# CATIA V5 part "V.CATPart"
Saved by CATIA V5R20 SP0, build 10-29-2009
Part number: V带轮
Material "无"
Material "Hall reflection"
Bounding box of the stored display mesh (mm): x -85 to 85, y -159.954 to 180.848, z -36.463 to 17.581
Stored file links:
  D:\liandongzhou\V.CATPart
  D:\catiaM\win_b64\startup\materials\Advanced_Materials.CATMaterial
  D:\catiaM\win_b64\startup\materials\shaders\CATIA_Environment_CUBEMap_Street_1024.dds
  D:\catiaM\win_b64\startup\materials\shaders\CATIA_Metal_Polished.cgfx
  D:\catiaM\win_b64\startup\materials\shaders\CATIA_Diffuse_2DMap_Fiber_256.dds
  D:\catiaM\win_b64\startup\materials\shaders\CATIA_Normal_2DMap_Fiber_1024.dds
  D:\catiaM\win_b64\startup\materials\shaders\CATIA_Leather_Rough.cgfx
  D:\catiaM\win_b64\startup\materials\textures\dot_grid2.png
  D:\catiaM\win_b64\startup\materials\textures\hex_grid.png
  D:\catiaM\win_b64\startup\materials\shaders\CATIA_Environment_2DMap_Street_2048.dds
  D:\catiaM\win_b64\startup\materials\shaders\CATIA_Normal_2DMap_Scratches_1024.dds
  D:\catiaM\win_b64\startup\materials\shaders\CATIA_Metal_Brushed.cgfx
  D:\catiaM\win_b64\startup\materials\environment_map\CATIA_Environment_2DMap_LightRedSatin_256.jpg
  D:\catiaM\win_b64\startup\materials\environment_map\CATIA_Environment_2DMap_DarkRedSatin_256.jpg
  D:\catiaM\win_b64\startup\materials\environment_map\CATIA_Environment_2DMap_Chroma1_256.jpg
  D:\catiaM\win_b64\startup\materials\textures\dot_grid.png
  D:\catiaM\win_b64\startup\materials\shaders\CATIA_Environment_2DMap_Hall_2048.dds
  D:\catiaM\win_b64\startup\materials\shaders\CATIA_Normal_2DMap_MZDotGrid_1024.dds
  D:\catiaM\win_b64\startup\materials\shaders\CATIA_Opacity_2DMap_MZDotGrid_1024.dds
  D:\catiaM\win_b64\startup\materials\shaders\CATIA_Metal_Grid.cgfx
  D:\catiaM\win_b64\startup\materials\environment_map\CATIA_Environment_2DMap_Satin_256.jpg
  D:\catiaM\win_b64\startup\materials\shaders\CATIA_Normal_2DMap_Leather_1024.dds
  D:\catiaM\win_b64\startup\materials\shaders\CATIA_Normal_2DMap_Noisemm_1024.dds
  D:\catiaM\win_b64\startup\materials\shaders\CATIA_Leather_BRDF.cgfx
  D:\catiaM\win_b64\startup\materials\shaders\CATIA_Plastic_Matt.cgfx
  D:\catiaM\win_b64\startup\materials\shaders\CATIA_Toon2.cgfx
  D:\catiaM\win_b64\startup\materials\shaders\CATIA_Environment_CUBEMap_Hall_1024.dds
  D:\catiaM\win_b64\startup\materials\shaders\CATIA_Anisotropy_2DMap_CarbonTwill2x2_1024.dds
  D:\catiaM\win_b64\startup\materials\shaders\CATIA_Carbon_Polished.cgfx
  D:\catiaM\win_b64\startup\materials\textures\square_grid.png
  D:\catiaM\win_b64\startup\materials\textures\wire_netting.png
  D:\catiaM\win_b64\startup\materials\shaders\CATIA_Diffuse_2DMap_WoodKing_512.dds
  D:\catiaM\win_b64\startup\materials\shaders\CATIA_Wood_Polished.cgfx
  D:\catiaM\win_b64\startup\materials\shaders\CATIA_Diffuse_2DMap_StoneWall_256.dds
  D:\catiaM\win_b64\startup\materials\shaders\CATIA_Normal_2DMap_StoneWall_512.dds
  D:\catiaM\win_b64\startup\materials\shaders\CATIA_Leather.cgfx
  D:\catiaM\win_b64\startup\materials\shaders\CATIA_Toon.cgfx
  D:\catiaM\win_b64\startup\materials\textures\speaker_grid.png
  D:\catiaM\win_b64\startup\materials\shaders\CATIA_Anisotropy_2DMap_CarbonPlain_1024.dds
  D:\catiaM\win_b64\startup\materials\environment_map\CATIA_Environment_2DMap_Garden_256.jpg
  D:\catiaM\win_b64\startup\materials\environment_map\CATIA_Environment_2DMap_Reflections_256.jpg
  D:\catiaM\win_b64\startup\materials\environment_map\CATIA_Environment_2DMap_NonLinear_256.jpg
  D:\catiaM\win_b64\startup\materials\environment_map\CATIA_Environment_2DMap_Soft_256.jpg
  D:\catiaM\win_b64\startup\materials\environment_map\CATIA_Environment_2DMap_Hangar_256.jpg
  D:\catiaM\win_b64\startup\materials\environment_map\CATIA_Environment_2DMap_Street_256.jpg
  D:\catiaM\win_b64\startup\materials\environment_map\CATIA_Environment_2DMap_Loft_256.jpg
  D:\catiaM\win_b64\startup\materials\environment_map\CATIA_Environment_2DMap_Hall_256.jpg
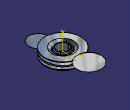
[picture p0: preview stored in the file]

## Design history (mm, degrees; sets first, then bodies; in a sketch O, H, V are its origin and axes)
Set1
  Sketch1 on xy-plane, origin (0, 0, 0), H (1, 0, 0), V (0, 1, 0)
    circle A1 centre (0, 0) radius 85
    radius A1 = 85
Body1 "pulley" (main body), material "Hall reflection"
  Pad1: profile Sketch1, direction (0, 0, 1), length 17.5
  Body2
    Sketch2 on yz-plane, origin (0, 0, 0), H (0, 1, 0), V (0, 0, 1)
      construction line L1 (0, 7.5) -> (110, 7.5)
      reference projected line E1 (-85, 17.5) -> (85, 17.5) from edge [face of Pad1 from Sketch1.A1 | end face of Pad1]
      construction line L2 (75, 40) -> (75, -50)
      construction line L3 (38.5278, 49.6475) -> (38.5278, -40.3525)
      construction line L4 (15.5531, 7.5) -> (119.2864, 18.4028)
      point P7 (15.5531, 7.5)
      axis line L5 (15.5531, 7.5) -> (130.7802, 0)
      point P9 (130.7802, 0)
      construction line L6 (93.2418, 15.6654) -> (93.2418, 2.4433)
      point P10 (93.2418, 15.6654)
      point P11 (93.2418, 2.4433)
      construction line L7 (75, 13.7481) -> (-21.9134, 13.7481)
      point P12 (75, 13.7481)
      construction line L8 (75, 3.6307) -> (-25.448, 3.6307)
      point P14 (75, 3.6307)
      point P16 (38.5278, 9.9147)
      line L9 (38.5278, 9.9147) -> (38.5278, 6.0046)
      point P17 (38.5278, 6.0046)
      line L10 (38.5278, 6.0046) -> (93.2418, 2.4433)
      line L11 (93.2418, 2.4433) -> (93.2418, 15.6654)
      line L12 (93.2418, 15.6654) -> (38.5278, 9.9147)
      distance L1 E1 = 10
      distance L2 V = 75
      angle L4 L1 = 6
      angle L1 L5 = 3.7241
      distance L8 L7 = 10.1175
      horizontal: L1 H, L7 H, L8 H
      vertical: L2 V, L3 V, L6 V, L9 V, L11 V
      coincidence: P7 L1, P9 H, P10 L4, P11 L5, P12 L4, P12 L2, P14 L5, P14 L2, P16 L4, P16 L3, P17 L5
      parallelism: L10 L5, L12 L4
    Shaft1: profile Sketch2, axis axis of face of Pad1 from Sketch1.A1, angle 360
  Remove1: tool Body2
  Sketch3 on end face of Pad1, origin (0, 0, 17.5), H (1, 0, 0), V (0, 1, 0)
    circle A1 centre (0, 0) radius 27.5
    radius A1 = 27.5
  Body3
    Pocket1: profile Sketch3, direction (0, 0, -1), length 17.5
  Remove2: tool Body3
  Sketch4 on zx-plane, origin (0, 0, 0), H (-1, 0, 0), V (0, 0, 1)
  Sketch5 on zx-plane, origin (0, 0, 0), H (-1, 0, 0), V (0, 0, 1)
    line L1 (27.5, 39.8229) -> (27.5, -18.0483)
    distance L1 V = 27.5
    vertical: L1 V
  Sketch6 on zx-plane, origin (0, 0, 0), H (-1, 0, 0), V (0, 0, 1)
    point P1 (48.6869, 24.3737)
    point P2 (24.3841, 8.9207)
    line L1 (28.9369, 20.5943) -> (31.5855, 8.9207)
    line L2 (31.5855, 8.9207) -> (35.3247, 8.9207)
    line L3 (35.3247, 8.9207) -> (57.4484, 20.5943)
    line L4 (57.4484, 20.5943) -> (28.9369, 20.5943)
    horizontal: L2 H, L4 H
  Sketch7 on zx-plane, origin (0, 0, 0), H (-1, 0, 0), V (0, 0, 1)
  Sketch8 on zx-plane, origin (0, 0, 0), H (-1, 0, 0), V (0, 0, 1)
  Sketch9 on zx-plane, origin (0, 0, 0), H (-1, 0, 0), V (0, 0, 1)
  Sketch10 on zx-plane, origin (0, 0, 0), H (-1, 0, 0), V (0, 0, 1)
  Sketch11 on zx-plane, origin (0, 0, 0), H (-1, 0, 0), V (0, 0, 1)
  Sketch12 on zx-plane, origin (0, 0, 0), H (-1, 0, 0), V (0, 0, 1)
    construction line L1 through (0, 0) direction (0, 1)
  Groove1: profile Sketch6, axis Z axis, angle 360
  Mirror1: of the body so far, about xy-plane
  Body4
    Sketch13 on yz-plane, origin (0, 0, 0), H (0, 1, 0), V (0, 0, 1)
      construction line L1 (136.949, -48.0927) -> (136.949, -55.6179)
      axis line L2 (-85.9645, -15.2557) -> (-205.3102, -15.2557)
      point P5 (-116.1439, -15.2557)
      line L3 (-116.1439, -15.2557) -> (-116.1439, -36.4634)
      line L4 (-116.1439, -36.4634) -> (-160.0412, -15.2557)
      point P7 (-160.0412, -15.2557)
      line L5 (-160.0412, -15.2557) -> (-116.1439, -15.2557)
      vertical: L1 V, L3 V
      horizontal: L2 H, L5 H
      coincidence: P5 L2, P7 L2
    Sketch14 on yz-plane, origin (0, 0, 0), H (0, 1, 0), V (0, 0, 1)
      construction line L1 (-114.7718, -33.0421) -> (-114.7718, 60.6817)
      axis line L2 (124.603, 17.5825) -> (124.603, -48.0927)
      vertical: L1 V, L2 V
    Sketch15 on yz-plane, origin (0, 0, 0), H (0, 1, 0), V (0, 0, 1)
    Sketch16 on yz-plane, origin (0, 0, 0), H (0, 1, 0), V (0, 0, 1)
    Sketch17 on yz-plane, origin (0, 0, 0), H (0, 1, 0), V (0, 0, 1)
      axis line L1 (123.919, 17.5814) -> (180.8482, 17.5814)
      line L2 (123.919, 17.5814) -> (123.919, 0)
      point P2 (123.919, 0)
      line L3 (123.919, 0) -> (180.8482, 17.5814)
      line L4 (180.8482, 17.5814) -> (123.919, 17.5814)
      horizontal: L1 H, L4 H
      coincidence: P2 H
      vertical: L2 V
    Shaft2: profile Sketch17, axis Sketch17.L2, angle 360
    Sketch18 on yz-plane, origin (0, 0, 0), H (0, 1, 0), V (0, 0, 1)
    Shaft3: profile Sketch13, axis Sketch13.L3, angle 360
  Assemble1: tool Body4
